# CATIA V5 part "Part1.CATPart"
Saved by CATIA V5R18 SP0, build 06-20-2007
Part number: Part1
Bounding box of the stored display mesh (mm): x -50 to 50, y -25 to 25, z -25 to 25
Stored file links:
  D:\Shriniwas\v5_r19\c16_CAT_v5r19\c16_Part\Sperical Joint\Part1.CATPart
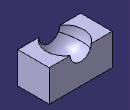
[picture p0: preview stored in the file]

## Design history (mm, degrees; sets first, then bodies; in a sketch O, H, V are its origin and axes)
Body1 (main body)
  Sketch1 on xy-plane, origin (0, 0, 0), H (1, 0, 0), V (0, 1, 0)
    line L1 (50, 25) -> (50, -25)
    line L2 (50, -25) -> (-50, -25)
    line L3 (-50, -25) -> (-50, 25)
    line L4 (-50, 25) -> (50, 25)
    length L4 = 100
    length L1 = 50
    vertical: L1 V, L3 V
    horizontal: L2 H, L4 H
    equidistance: L1 L3 O, L2 L4 O
  Pad1: profile Sketch1, direction (0, 0, 1), length 25, mirrored extent
  Sketch2 on end face of Pad1, origin (0, 0, 25), H (1, 0, 0), V (0, 1, 0)
    line L1 (0, -30) -> (0, 30)
    point P1 (0, -30)
    point P2 (0, 30)
    arc A1 centre (0, 0) radius 30 from (0, -30) to (0, 30) ccw
    point P3 (0, 30)
    radius A1 = 30
    coincidence: P1 V, P3 P2
    vertical: L1 V
  Groove1: profile Sketch2, axis Sketch2.L1, angle 360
